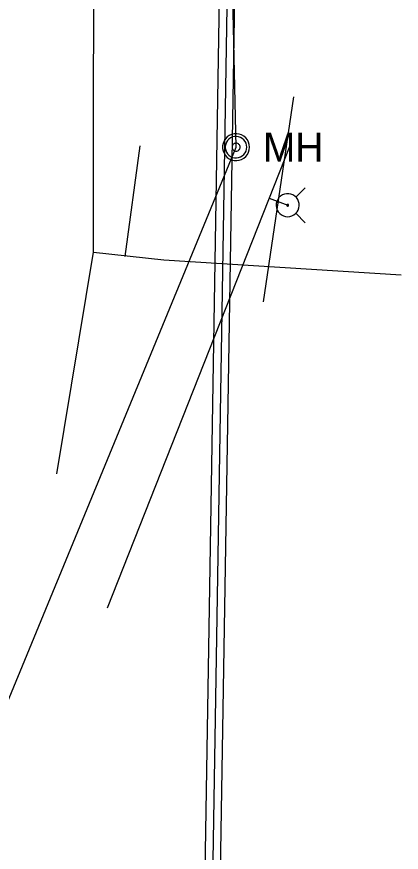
# Model space of a CAD drawing. Extents: x 600849 to 606371, y 330010 to 403088.
# Drawn here: x 603848.5 to 603935.8, y 337740.7 to 337930.3 of the extents above; entities that cross this region are included whole.
import ezdxf

# ---------------------------------------------------------------- set-up
doc = ezdxf.new("R2010")
doc.units = 0
for name, color, linetype in [('E_DRN_Pipe', 7, 'Continuous'), ('E_UTL_G_UG', 7, 'Continuous'), ('E_UTL_SAN', 7, 'Continuous'), ('E_UTL_SAN_UG', 7, 'Continuous'), ('E_UTL_SAN_UG_MMSD', 7, 'Continuous'), ('E_UTL_SAN_UG_OUTER_LIMITS', 7, 'Continuous'), ('E_UTL_W_UG', 7, 'Continuous'), ('E_UTL_WHydrant', 7, 'Continuous')]:
    doc.layers.add(name, color=color, linetype=linetype)

# ---------------------------------------------------------------- blocks, each defined once
blk = doc.blocks.new('ACAD_PROXY_ENTITY_12')
at = {"layer": 'E_UTL_SAN'}
for points in [[(1841881.85, 1030282.67), (1841881.68, 1030284.44), (1841881.18, 1030286.13), (1841880.37, 1030287.71), (1841879.28, 1030289.1), (1841877.94, 1030290.26), (1841876.41, 1030291.15), (1841874.73, 1030291.72), (1841872.98, 1030291.98), (1841871.21, 1030291.89), (1841869.49, 1030291.47), (1841867.88, 1030290.74), (1841866.44, 1030289.71), (1841865.22, 1030288.43), (1841864.26, 1030286.94), (1841863.6, 1030285.3), (1841863.27, 1030283.56), (1841863.27, 1030281.79), (1841863.6, 1030280.05), (1841864.26, 1030278.41), (1841865.22, 1030276.92), (1841866.44, 1030275.63), (1841867.88, 1030274.61), (1841869.49, 1030273.87), (1841871.21, 1030273.45), (1841872.98, 1030273.37), (1841874.73, 1030273.62), (1841876.41, 1030274.2), (1841877.94, 1030275.09), (1841879.28, 1030276.25), (1841880.37, 1030277.64), (1841881.18, 1030279.21), (1841881.68, 1030280.91), (1841881.85, 1030282.67)], [(1841879.99, 1030282.67), (1841879.85, 1030284.08), (1841879.45, 1030285.44), (1841878.8, 1030286.7), (1841877.93, 1030287.81), (1841876.86, 1030288.74), (1841875.63, 1030289.45), (1841874.29, 1030289.91), (1841872.89, 1030290.12), (1841871.48, 1030290.05), (1841870.1, 1030289.71), (1841868.81, 1030289.13), (1841867.66, 1030288.3), (1841866.68, 1030287.28), (1841865.91, 1030286.09), (1841865.39, 1030284.77), (1841865.12, 1030283.38), (1841865.12, 1030281.97), (1841865.39, 1030280.57), (1841865.91, 1030279.26), (1841866.68, 1030278.07), (1841867.66, 1030277.04), (1841868.81, 1030276.22), (1841870.1, 1030275.63), (1841871.48, 1030275.3), (1841872.89, 1030275.23), (1841874.29, 1030275.43), (1841875.63, 1030275.9), (1841876.86, 1030276.6), (1841877.93, 1030277.53), (1841878.8, 1030278.65), (1841879.45, 1030279.9), (1841879.85, 1030281.26), (1841879.99, 1030282.67)], [(1841875.33, 1030282.67), (1841875.28, 1030283.2), (1841875.13, 1030283.71), (1841874.89, 1030284.18), (1841874.56, 1030284.6), (1841874.16, 1030284.95), (1841873.7, 1030285.21), (1841873.2, 1030285.39), (1841872.67, 1030285.46), (1841872.14, 1030285.44), (1841871.62, 1030285.31), (1841871.14, 1030285.09), (1841870.71, 1030284.78), (1841870.34, 1030284.4), (1841870.05, 1030283.95), (1841869.86, 1030283.46), (1841869.76, 1030282.94), (1841869.76, 1030282.41), (1841869.86, 1030281.89), (1841870.05, 1030281.39), (1841870.34, 1030280.95), (1841870.71, 1030280.56), (1841871.14, 1030280.25), (1841871.62, 1030280.03), (1841872.14, 1030279.91), (1841872.67, 1030279.88), (1841873.2, 1030279.96), (1841873.7, 1030280.13), (1841874.16, 1030280.4), (1841874.56, 1030280.75), (1841874.89, 1030281.16), (1841875.13, 1030281.63), (1841875.28, 1030282.14), (1841875.33, 1030282.67)]]:
    blk.add_lwpolyline(points, dxfattribs=at)
blk.add_text('MH', height=20.117, dxfattribs=at).set_placement((1841891.16, 1030272.61))
blk = doc.blocks.new('ACAD_PROXY_ENTITY_13')
at = {"layer": 'E_UTL_WHydrant'}
for points in [[(1844020.51, 1030441.91), (1844027.04, 1030448.45)], [(1844014.92, 1030428.33), (1844016.43, 1030428.47), (1844017.89, 1030428.9), (1844019.24, 1030429.6), (1844020.43, 1030430.54), (1844021.43, 1030431.69), (1844022.19, 1030433), (1844022.68, 1030434.44), (1844022.9, 1030435.94), (1844022.83, 1030437.46), (1844022.47, 1030438.94), (1844021.84, 1030440.32), (1844020.96, 1030441.56), (1844019.86, 1030442.61), (1844018.58, 1030443.43), (1844017.17, 1030443.99), (1844015.68, 1030444.28), (1844014.16, 1030444.28), (1844012.66, 1030443.99), (1844011.25, 1030443.43), (1844009.97, 1030442.61), (1844008.87, 1030441.56), (1844007.99, 1030440.32), (1844007.36, 1030438.94), (1844007, 1030437.46), (1844006.93, 1030435.94), (1844007.15, 1030434.44), (1844007.64, 1030433), (1844008.4, 1030431.69), (1844009.4, 1030430.54), (1844010.59, 1030429.6), (1844011.94, 1030428.9), (1844013.4, 1030428.47), (1844014.92, 1030428.33)], [(1844014.92, 1030435.71), (1844015.03, 1030435.72), (1844015.14, 1030435.76), (1844015.25, 1030435.81), (1844015.34, 1030435.88), (1844015.41, 1030435.97), (1844015.47, 1030436.07), (1844015.51, 1030436.18), (1844015.53, 1030436.3), (1844015.52, 1030436.41), (1844015.49, 1030436.52), (1844015.45, 1030436.63), (1844015.38, 1030436.72), (1844015.29, 1030436.8), (1844015.2, 1030436.87), (1844015.09, 1030436.91), (1844014.97, 1030436.93), (1844014.86, 1030436.93), (1844014.74, 1030436.91), (1844014.64, 1030436.87), (1844014.54, 1030436.8), (1844014.45, 1030436.72), (1844014.39, 1030436.63), (1844014.34, 1030436.52), (1844014.31, 1030436.41), (1844014.3, 1030436.3), (1844014.32, 1030436.18), (1844014.36, 1030436.07), (1844014.42, 1030435.97), (1844014.49, 1030435.88), (1844014.59, 1030435.81), (1844014.69, 1030435.76), (1844014.8, 1030435.72), (1844014.92, 1030435.71)], [(1844020.51, 1030430.73), (1844027.04, 1030424.2)]]:
    blk.add_lwpolyline(points, dxfattribs=at)

msp = doc.modelspace()

# ---------------------------------------------------------------- linework, layer by layer
at = {"layer": 'E_DRN_Pipe'}
for p, q in [((603904.52, 337865.65), (603911.46, 337912.18)), ((603873.14, 337875.9), (603876.51, 337901.06))]:
    msp.add_line(p, q, dxfattribs=at)
at = {"layer": 'E_UTL_G_UG'}
for points in [[(603857.61, 337826.63), (603865.95, 337876.92), (603866.02, 337966.94), (603882.73, 337968.38), (603883.92, 338010.64)], [(603865.95, 337876.92), (603881.93, 337875.2), (603935.84, 337871.78)]]:
    msp.add_lwpolyline(points, dxfattribs=at)
at = {"layer": 'E_UTL_SAN_UG'}
for p, q in [((603898.31, 337900.75), (603895.55, 338024.99)), ((603838.09, 337754.66), (603898.31, 337900.75))]:
    msp.add_line(p, q, dxfattribs=at)
at = {"layer": 'E_UTL_SAN_UG_MMSD'}
msp.add_lwpolyline([(603886.8, 337355.91), (603897.65, 338015.63)], dxfattribs=at)
at = {"layer": 'E_UTL_SAN_UG_OUTER_LIMITS'}
for p, q in [((603885.05, 337355.94), (603895.92, 338017.08)), ((603888.55, 337355.88), (603899.38, 338014.52))]:
    msp.add_line(p, q, dxfattribs=at)
at = {"layer": 'E_UTL_W_UG'}
for p, q in [((603869.13, 337796.16), (603910.57, 337901.11)), ((603905.87, 337889.19), (603910.05, 337887.54))]:
    msp.add_line(p, q, dxfattribs=at)

# ---------------------------------------------------------------- block references
at = {"layer": 'E_UTL_SAN', "xscale": 0.32808333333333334, "yscale": 0.32808333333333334}
msp.add_blockref('ACAD_PROXY_ENTITY_12', (-389.37, -117.83), dxfattribs=at)
at = {"layer": 'E_UTL_WHydrant', "xscale": 0.32808333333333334, "yscale": 0.32808333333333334}
msp.add_blockref('ACAD_PROXY_ENTITY_13', (-1080.52, -181.42), dxfattribs=at)

doc.saveas('drawing.dxf')
